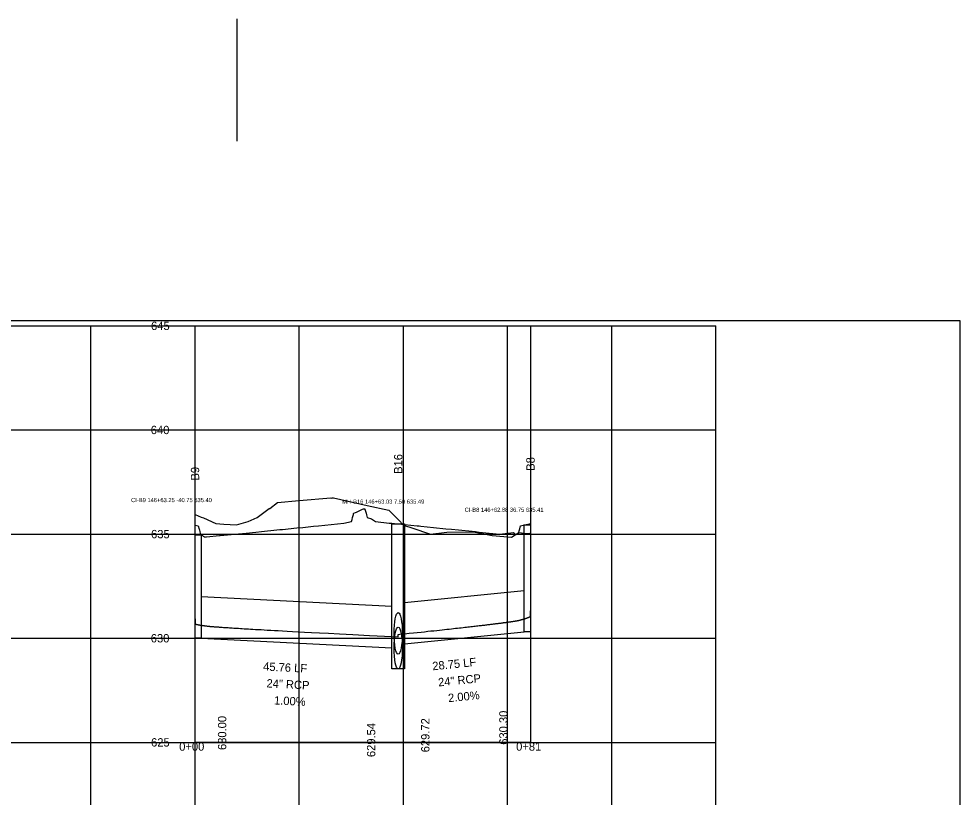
# Model space of a CAD drawing. Extents: x 2253035 to 2279930, y 13774972 to 13793443.
# Drawn here: x 2277907.1 to 2278133, y 13792678.1 to 13792865 of the extents above; entities that cross this region are included whole.
import ezdxf

# ---------------------------------------------------------------- set-up
doc = ezdxf.new("R2010")
doc.units = 0
for name, color, linetype in [('Default', 7, 'Continuous'), ('E_Utility_ATT_HH', 7, 'Continuous'), ('E_Utility_ATT_PR_PVC', 7, 'Continuous'), ('E_Utility_Electric_Power Pole_PP_point', 7, 'Continuous'), ('E_Utility_Telephone_Manhole Telephone_MHT_point', 7, 'Continuous'), ('E_Utility_Telephone_Telephone Pedestal_TPED_Description', 7, 'Continuous'), ('E_Utility_Water_Water Meter_WM_Description', 7, 'Continuous'), ('E_Utillity_Water_Water Line_12in', 7, 'Continuous'), ('E_Utillity_Water_Water Line_1in', 7, 'Continuous'), ('E_Utillity_Water_Water Line_4in', 7, 'Continuous'), ('E_Utillity_Water_Water Line_8in', 7, 'Continuous')]:
    doc.layers.add(name, color=color, linetype=linetype)

msp = doc.modelspace()

# ---------------------------------------------------------------- linework, layer by layer
at = {"layer": 'Default'}
for p, q in [((2277949.4, 13792766.27), (2278029.91, 13792766.27)), ((2277949.4, 13792741.27), (2278029.91, 13792741.27)), ((2277949.4, 13792716.27), (2278029.91, 13792716.27))]:
    msp.add_line(p, q, dxfattribs=at)
msp.add_lwpolyline([(2277949.4, 13792691.27), (2277949.4, 13792791.27), (2278029.91, 13792791.27), (2278029.91, 13792691.27)], close=True, dxfattribs=at)
at = {"layer": 'E_Utility_ATT_PR_PVC'}
msp.add_line((2277998.16, 13792716.59), (2277998.16, 13792717.18), dxfattribs=at)
for points in [[(2277998.16, 13792717.18), (2277998.55, 13792717.22), (2277999.7, 13792717.34), (2278000.78, 13792717.45), (2278001.79, 13792717.56), (2278002.73, 13792717.66), (2278003.63, 13792717.75), (2278004.47, 13792717.84), (2278005.26, 13792717.93), (2278006.02, 13792718.01), (2278006.74, 13792718.08), (2278007.42, 13792718.16), (2278008.07, 13792718.23), (2278008.69, 13792718.29), (2278009.29, 13792718.36), (2278009.86, 13792718.42), (2278010.41, 13792718.48), (2278010.93, 13792718.54), (2278011.44, 13792718.59), (2278011.93, 13792718.65), (2278012.4, 13792718.7), (2278012.85, 13792718.75), (2278013.28, 13792718.8), (2278013.71, 13792718.85), (2278014.11, 13792718.89), (2278014.51, 13792718.94), (2278014.89, 13792718.98), (2278015.26, 13792719.02), (2278015.62, 13792719.06), (2278015.96, 13792719.1), (2278016.3, 13792719.14), (2278016.63, 13792719.18), (2278016.94, 13792719.21), (2278017.25, 13792719.25), (2278017.55, 13792719.29), (2278017.84, 13792719.32), (2278018.12, 13792719.35), (2278018.4, 13792719.39), (2278018.67, 13792719.42), (2278018.93, 13792719.45), (2278019.18, 13792719.48), (2278019.43, 13792719.51), (2278019.67, 13792719.54), (2278019.91, 13792719.57), (2278020.14, 13792719.59), (2278020.36, 13792719.62), (2278020.58, 13792719.65), (2278020.79, 13792719.67), (2278021, 13792719.7), (2278021.2, 13792719.73), (2278021.4, 13792719.75), (2278021.6, 13792719.78), (2278021.79, 13792719.8), (2278021.97, 13792719.82), (2278022.15, 13792719.85), (2278022.33, 13792719.87), (2278022.5, 13792719.89), (2278022.67, 13792719.91), (2278022.84, 13792719.93), (2278023, 13792719.96), (2278023.16, 13792719.98), (2278023.31, 13792720), (2278023.46, 13792720.02), (2278023.61, 13792720.04), (2278023.75, 13792720.06), (2278023.9, 13792720.08), (2278024.04, 13792720.09), (2278024.17, 13792720.11), (2278024.3, 13792720.13), (2278024.43, 13792720.15), (2278024.56, 13792720.17), (2278024.69, 13792720.18), (2278024.81, 13792720.2), (2278024.93, 13792720.22), (2278025.05, 13792720.24), (2278025.16, 13792720.25), (2278025.28, 13792720.27), (2278025.39, 13792720.28), (2278025.49, 13792720.3), (2278025.6, 13792720.32), (2278025.7, 13792720.33), (2278025.81, 13792720.35), (2278025.91, 13792720.36), (2278026, 13792720.38), (2278026.1, 13792720.39), (2278026.19, 13792720.4), (2278026.29, 13792720.42), (2278026.38, 13792720.43), (2278026.46, 13792720.45), (2278026.55, 13792720.46), (2278026.64, 13792720.47), (2278026.72, 13792720.49), (2278026.8, 13792720.5), (2278026.88, 13792720.51), (2278026.96, 13792720.53), (2278027.04, 13792720.55), (2278027.11, 13792720.57), (2278027.19, 13792720.59), (2278027.26, 13792720.61), (2278027.33, 13792720.63), (2278027.4, 13792720.65), (2278027.47, 13792720.67), (2278027.53, 13792720.69), (2278027.6, 13792720.7), (2278027.66, 13792720.72), (2278027.72, 13792720.74), (2278027.79, 13792720.76), (2278027.85, 13792720.77), (2278027.91, 13792720.79), (2278027.96, 13792720.81), (2278028.02, 13792720.82), (2278028.08, 13792720.84), (2278028.13, 13792720.85), (2278028.18, 13792720.87), (2278028.23, 13792720.89), (2278028.29, 13792720.9), (2278028.34, 13792720.92), (2278028.38, 13792720.93), (2278028.43, 13792720.95), (2278028.48, 13792720.96), (2278028.52, 13792720.97), (2278028.57, 13792720.99), (2278028.61, 13792721), (2278028.66, 13792721.02), (2278028.7, 13792721.03), (2278028.74, 13792721.04), (2278028.78, 13792721.05), (2278028.82, 13792721.07), (2278028.86, 13792721.08), (2278028.89, 13792721.09), (2278028.93, 13792721.1), (2278028.97, 13792721.12), (2278029, 13792721.13), (2278029.03, 13792721.14), (2278029.07, 13792721.15), (2278029.1, 13792721.16), (2278029.13, 13792721.18), (2278029.16, 13792721.19), (2278029.19, 13792721.2), (2278029.22, 13792721.21), (2278029.25, 13792721.22), (2278029.28, 13792721.23), (2278029.3, 13792721.24), (2278029.33, 13792721.25), (2278029.36, 13792721.26), (2278029.38, 13792721.27), (2278029.41, 13792721.28), (2278029.43, 13792721.29), (2278029.45, 13792721.3), (2278029.47, 13792721.31), (2278029.5, 13792721.32), (2278029.52, 13792721.33), (2278029.54, 13792721.34), (2278029.56, 13792721.35), (2278029.58, 13792721.35), (2278029.59, 13792721.36), (2278029.61, 13792721.37), (2278029.63, 13792721.38), (2278029.65, 13792721.39), (2278029.66, 13792721.4), (2278029.68, 13792721.4), (2278029.69, 13792721.41), (2278029.71, 13792721.42), (2278029.72, 13792721.43), (2278029.73, 13792721.44), (2278029.75, 13792721.44), (2278029.76, 13792721.45), (2278029.77, 13792721.46), (2278029.78, 13792721.47), (2278029.79, 13792721.47), (2278029.8, 13792721.48), (2278029.81, 13792721.49), (2278029.82, 13792721.49), (2278029.83, 13792721.5), (2278029.84, 13792721.51), (2278029.85, 13792721.51), (2278029.86, 13792721.52), (2278029.86, 13792721.53), (2278029.87, 13792721.53), (2278029.87, 13792721.54), (2278029.88, 13792721.55), (2278029.88, 13792721.55), (2278029.89, 13792721.56), (2278029.89, 13792721.56), (2278029.9, 13792721.57), (2278029.9, 13792721.57), (2278029.9, 13792721.58), (2278029.91, 13792721.59), (2278029.91, 13792721.59), (2278029.91, 13792721.6), (2278029.91, 13792721.6), (2278029.91, 13792721.61), (2278029.91, 13792721.61), (2278029.91, 13792721.62), (2278029.91, 13792722.84)], [(2277949.4, 13792720.95), (2277949.4, 13792719.77), (2277949.4, 13792719.77), (2277949.41, 13792719.76), (2277949.41, 13792719.76), (2277949.41, 13792719.75), (2277949.42, 13792719.75), (2277949.42, 13792719.74), (2277949.43, 13792719.74), (2277949.44, 13792719.73), (2277949.45, 13792719.72), (2277949.46, 13792719.72), (2277949.47, 13792719.71), (2277949.48, 13792719.71), (2277949.5, 13792719.7), (2277949.51, 13792719.69), (2277949.53, 13792719.69), (2277949.55, 13792719.68), (2277949.57, 13792719.67), (2277949.59, 13792719.66), (2277949.62, 13792719.66), (2277949.64, 13792719.65), (2277949.67, 13792719.64), (2277949.7, 13792719.63), (2277949.73, 13792719.63), (2277949.76, 13792719.62), (2277949.79, 13792719.61), (2277949.83, 13792719.6), (2277949.86, 13792719.59), (2277949.9, 13792719.58), (2277949.94, 13792719.57), (2277949.98, 13792719.57), (2277950.03, 13792719.56), (2277950.07, 13792719.55), (2277950.12, 13792719.54), (2277950.17, 13792719.53), (2277950.23, 13792719.52), (2277950.28, 13792719.51), (2277950.34, 13792719.49), (2277950.4, 13792719.48), (2277950.46, 13792719.47), (2277950.52, 13792719.46), (2277950.59, 13792719.45), (2277950.66, 13792719.44), (2277950.73, 13792719.43), (2277950.8, 13792719.41), (2277950.88, 13792719.4), (2277950.96, 13792719.39), (2277951.04, 13792719.37), (2277951.13, 13792719.36), (2277951.22, 13792719.35), (2277951.31, 13792719.33), (2277951.41, 13792719.32), (2277951.51, 13792719.3), (2277951.61, 13792719.29), (2277951.71, 13792719.27), (2277951.82, 13792719.26), (2277951.94, 13792719.24), (2277952.05, 13792719.22), (2277952.17, 13792719.21), (2277952.3, 13792719.19), (2277952.43, 13792719.17), (2277952.56, 13792719.16), (2277952.7, 13792719.15), (2277952.84, 13792719.14), (2277952.99, 13792719.12), (2277953.15, 13792719.11), (2277953.3, 13792719.1), (2277953.47, 13792719.08), (2277953.64, 13792719.07), (2277953.81, 13792719.06), (2277953.99, 13792719.04), (2277954.18, 13792719.03), (2277954.38, 13792719.01), (2277954.58, 13792719), (2277954.79, 13792718.98), (2277955, 13792718.97), (2277955.23, 13792718.95), (2277955.46, 13792718.94), (2277955.7, 13792718.92), (2277955.95, 13792718.9), (2277956.21, 13792718.88), (2277956.48, 13792718.86), (2277956.76, 13792718.85), (2277957.05, 13792718.83), (2277957.35, 13792718.81), (2277957.67, 13792718.78), (2277958, 13792718.76), (2277958.34, 13792718.74), (2277958.69, 13792718.72), (2277959.07, 13792718.69), (2277959.45, 13792718.67), (2277959.86, 13792718.65), (2277960.28, 13792718.62), (2277960.73, 13792718.59), (2277961.2, 13792718.56), (2277961.69, 13792718.53), (2277962.2, 13792718.5), (2277962.74, 13792718.47), (2277963.31, 13792718.44), (2277963.92, 13792718.4), (2277964.56, 13792718.37), (2277965.24, 13792718.33), (2277965.96, 13792718.29), (2277966.73, 13792718.24), (2277967.56, 13792718.2), (2277968.44, 13792718.15), (2277969.39, 13792718.09), (2277970.43, 13792718.04), (2277971.55, 13792717.98), (2277972.78, 13792717.91), (2277974.13, 13792717.84), (2277975.64, 13792717.76), (2277977.32, 13792717.67), (2277979.24, 13792717.57), (2277981.46, 13792717.45), (2277984.08, 13792717.31), (2277987.25, 13792717.15), (2277991.27, 13792716.94), (2277996.72, 13792716.67), (2277998.16, 13792716.59)]]:
    msp.add_lwpolyline(points, dxfattribs=at)
at = {"layer": 'E_Utility_Electric_Power Pole_PP_point'}
msp.add_line((2277959.48, 13792835.56), (2277959.48, 13792864.97), dxfattribs=at)
at = {"layer": 'E_Utility_Telephone_Manhole Telephone_MHT_point'}
for p, q in [((2277749.4, 13792791.27), (2278074.4, 13792791.27)), ((2277924.4, 13792491.27), (2277924.4, 13792791.27)), ((2277949.4, 13792491.27), (2277949.4, 13792791.27)), ((2277974.4, 13792491.27), (2277974.4, 13792791.27)), ((2277999.4, 13792491.27), (2277999.4, 13792791.27)), ((2278024.4, 13792491.27), (2278024.4, 13792791.27)), ((2278049.4, 13792491.27), (2278049.4, 13792791.27)), ((2278074.4, 13792491.27), (2278074.4, 13792791.27)), ((2277749.4, 13792766.27), (2278074.4, 13792766.27)), ((2277749.4, 13792741.27), (2278074.4, 13792741.27)), ((2277749.4, 13792716.27), (2278074.4, 13792716.27)), ((2277749.4, 13792691.27), (2278074.4, 13792691.27))]:
    msp.add_line(p, q, dxfattribs=at)
at = {"layer": 'E_Utility_Water_Water Meter_WM_Description'}
msp.add_lwpolyline([(2278133.03, 13792792.44), (2277749.4, 13792792.44), (2277749.4, 13792491.27), (2278133.03, 13792491.27)], close=True, dxfattribs=at)
at = {"layer": 'E_Utillity_Water_Water Line_12in'}
for points in [[(2277996.66, 13792743.72), (2277999.66, 13792743.72), (2277999.66, 13792708.92), (2277996.66, 13792708.92)], [(2278028.41, 13792743.47), (2278029.91, 13792743.47), (2278029.91, 13792717.77), (2278028.41, 13792717.77)], [(2277949.4, 13792741.12), (2277950.9, 13792741.12), (2277950.9, 13792716.27), (2277949.4, 13792716.27)]]:
    msp.add_lwpolyline(points, close=True, dxfattribs=at)
at = {"layer": 'E_Utillity_Water_Water Line_1in'}
msp.add_lwpolyline([(2277949.4, 13792745.94), (2277950.9, 13792745.37), (2277950.9, 13792745.37), (2277951.44, 13792745.17), (2277954.42, 13792743.83), (2277956.34, 13792743.68), (2277959.38, 13792743.46), (2277962.14, 13792744.27), (2277964.31, 13792745.29), (2277967.23, 13792747.39), (2277967.38, 13792747.39), (2277969.23, 13792748.89), (2277974.39, 13792749.37), (2277982.01, 13792749.97), (2277982.21, 13792749.88), (2277982.42, 13792749.97), (2277982.66, 13792749.95), (2277990.69, 13792748.1), (2277995.92, 13792747.05), (2277996.66, 13792746.28), (2277996.66, 13792746.28), (2277998.16, 13792744.74), (2277998.16, 13792744.74), (2277999.53, 13792743.34), (2277999.66, 13792743.3), (2277999.66, 13792743.3), (2278001.46, 13792742.77), (2278005.94, 13792741.24), (2278009.81, 13792741.74), (2278016.25, 13792741.8), (2278020.7, 13792740.91), (2278025.33, 13792740.51), (2278027.1, 13792741.69), (2278028.41, 13792741.46), (2278028.41, 13792741.46), (2278028.62, 13792741.43), (2278029.57, 13792741.48), (2278029.91, 13792741.43)], dxfattribs=at)
at = {"layer": 'E_Utillity_Water_Water Line_4in'}
for p, q in [((2277999.66, 13792724.89), (2278028.41, 13792727.77)), ((2277950.9, 13792726.27), (2277996.66, 13792723.98)), ((2277950.9, 13792716.27), (2277996.66, 13792713.98)), ((2277999.66, 13792714.89), (2278028.41, 13792717.77))]:
    msp.add_line(p, q, dxfattribs=at)
for centre in [(2277998.16, 13792717.43), (2277998.16, 13792713.92)]:
    msp.add_ellipse(centre, major_axis=(0, 5), ratio=0.2, dxfattribs=at)
at = {"layer": 'E_Utillity_Water_Water Line_8in'}
msp.add_lwpolyline([(2277949.4, 13792743.39), (2277950.19, 13792743.27), (2277950.4, 13792742.43), (2277950.44, 13792742.27), (2277950.56, 13792741.83), (2277950.64, 13792741.51), (2277950.7, 13792741.27), (2277950.75, 13792741.08), (2277950.88, 13792741.14), (2277950.9, 13792741.12), (2277950.9, 13792741.12), (2277951.22, 13792740.91), (2277951.36, 13792740.8), (2277951.55, 13792740.67), (2277951.64, 13792740.61), (2277951.68, 13792740.58), (2277951.69, 13792740.58), (2277951.73, 13792740.55), (2277952.01, 13792740.58), (2277952.06, 13792740.58), (2277952.12, 13792740.59), (2277955.28, 13792740.9), (2277955.4, 13792740.91), (2277958.95, 13792741.27), (2277961.64, 13792741.53), (2277963.98, 13792741.77), (2277965.35, 13792741.9), (2277969.01, 13792742.27), (2277969.77, 13792742.34), (2277970.42, 13792742.41), (2277973.8, 13792742.74), (2277975.3, 13792742.89), (2277977.23, 13792743.08), (2277977.81, 13792743.14), (2277979.06, 13792743.27), (2277985.1, 13792743.88), (2277986.96, 13792744.27), (2277987.1, 13792744.79), (2277987.22, 13792745.27), (2277987.41, 13792746.01), (2277987.46, 13792746.18), (2277987.48, 13792746.27), (2277987.89, 13792746.42), (2277988.13, 13792746.54), (2277989.56, 13792747.27), (2277989.86, 13792747.31), (2277990.16, 13792747.36), (2277990.17, 13792747.32), (2277990.17, 13792747.3), (2277990.18, 13792747.27), (2277990.36, 13792746.57), (2277990.44, 13792746.27), (2277990.53, 13792745.93), (2277990.7, 13792745.27), (2277991.78, 13792744.95), (2277992.68, 13792744.27), (2277996.02, 13792743.93), (2277996.63, 13792743.87), (2277996.66, 13792743.87), (2277996.66, 13792743.87), (2277997.28, 13792743.81), (2277998.16, 13792743.72), (2277998.16, 13792743.72), (2277999.66, 13792743.57), (2277999.66, 13792743.57), (2278002.68, 13792743.27), (2278003.16, 13792743.22), (2278003.57, 13792743.18), (2278006.64, 13792742.87), (2278009.58, 13792742.57), (2278010.92, 13792742.44), (2278012.62, 13792742.27), (2278015.91, 13792741.94), (2278016.7, 13792741.86), (2278017.59, 13792741.77), (2278020.01, 13792741.52), (2278022.57, 13792741.27), (2278025.8, 13792741.69), (2278026.23, 13792741.27), (2278026.9, 13792741.27), (2278027.02, 13792741.27), (2278027.22, 13792742.04), (2278027.28, 13792742.27), (2278027.34, 13792742.52), (2278027.54, 13792743.27), (2278027.79, 13792743.35), (2278028.24, 13792743.43), (2278028.41, 13792743.47), (2278028.41, 13792743.47), (2278028.57, 13792743.5), (2278029.91, 13792743.81)], dxfattribs=at)

# ---------------------------------------------------------------- texts
at = {"layer": 'Default'}
for s, p in [('645', (2277938.85, 13792790.27)), ('640', (2277938.78, 13792765.27)), ('635', (2277938.85, 13792740.27)), ('630', (2277938.78, 13792715.27)), ('625', (2277938.85, 13792690.27)), ('0+00', (2277945.6, 13792689.27)), ('0+81', (2278026.46, 13792689.27))]:
    msp.add_text(s, height=2, dxfattribs=at).set_placement(p)
at = {"layer": 'E_Utility_ATT_HH'}
for s, rotation, p in [('B16', 90, (2277999.16, 13792755.74)), ('B8', 90, (2278030.91, 13792756.47)), ('B9', 90, (2277950.4, 13792754.13)), ('28.75 LF', 5.7106, (2278006.44, 13792708.57)), ('45.76 LF', 357.1376, (2277965.71, 13792708.53)), ('24" RCP', 5.7106, (2278007.84, 13792704.69)), ('24" RCP', 357.1376, (2277966.51, 13792704.48)), ('1.00%', 357.1376, (2277968.32, 13792700.39)), ('2.00%', 5.7106, (2278010.23, 13792700.91)), ('630.30', 90, (2278024.41, 13792690.7)), ('630.00', 90, (2277956.9, 13792689.44)), ('629.54', 90, (2277992.66, 13792687.74)), ('629.72', 90, (2278005.66, 13792688.89))]:
    msp.add_text(s, height=2, rotation=rotation, dxfattribs=at).set_placement(p)
at = {"layer": 'E_Utility_Telephone_Telephone Pedestal_TPED_Description'}
for s, p in [('CI-B9 146+63.25 -40.75 635.40', (2277934.06, 13792748.94)), ('MH-B16 146+63.03 7.50 635.49', (2277984.74, 13792748.57)), ('CI-B8 146+62.88 36.75 635.41', (2278014.1, 13792746.61))]:
    msp.add_text(s, height=1, rotation=0, dxfattribs=at).set_placement(p)

doc.saveas('drawing.dxf')
